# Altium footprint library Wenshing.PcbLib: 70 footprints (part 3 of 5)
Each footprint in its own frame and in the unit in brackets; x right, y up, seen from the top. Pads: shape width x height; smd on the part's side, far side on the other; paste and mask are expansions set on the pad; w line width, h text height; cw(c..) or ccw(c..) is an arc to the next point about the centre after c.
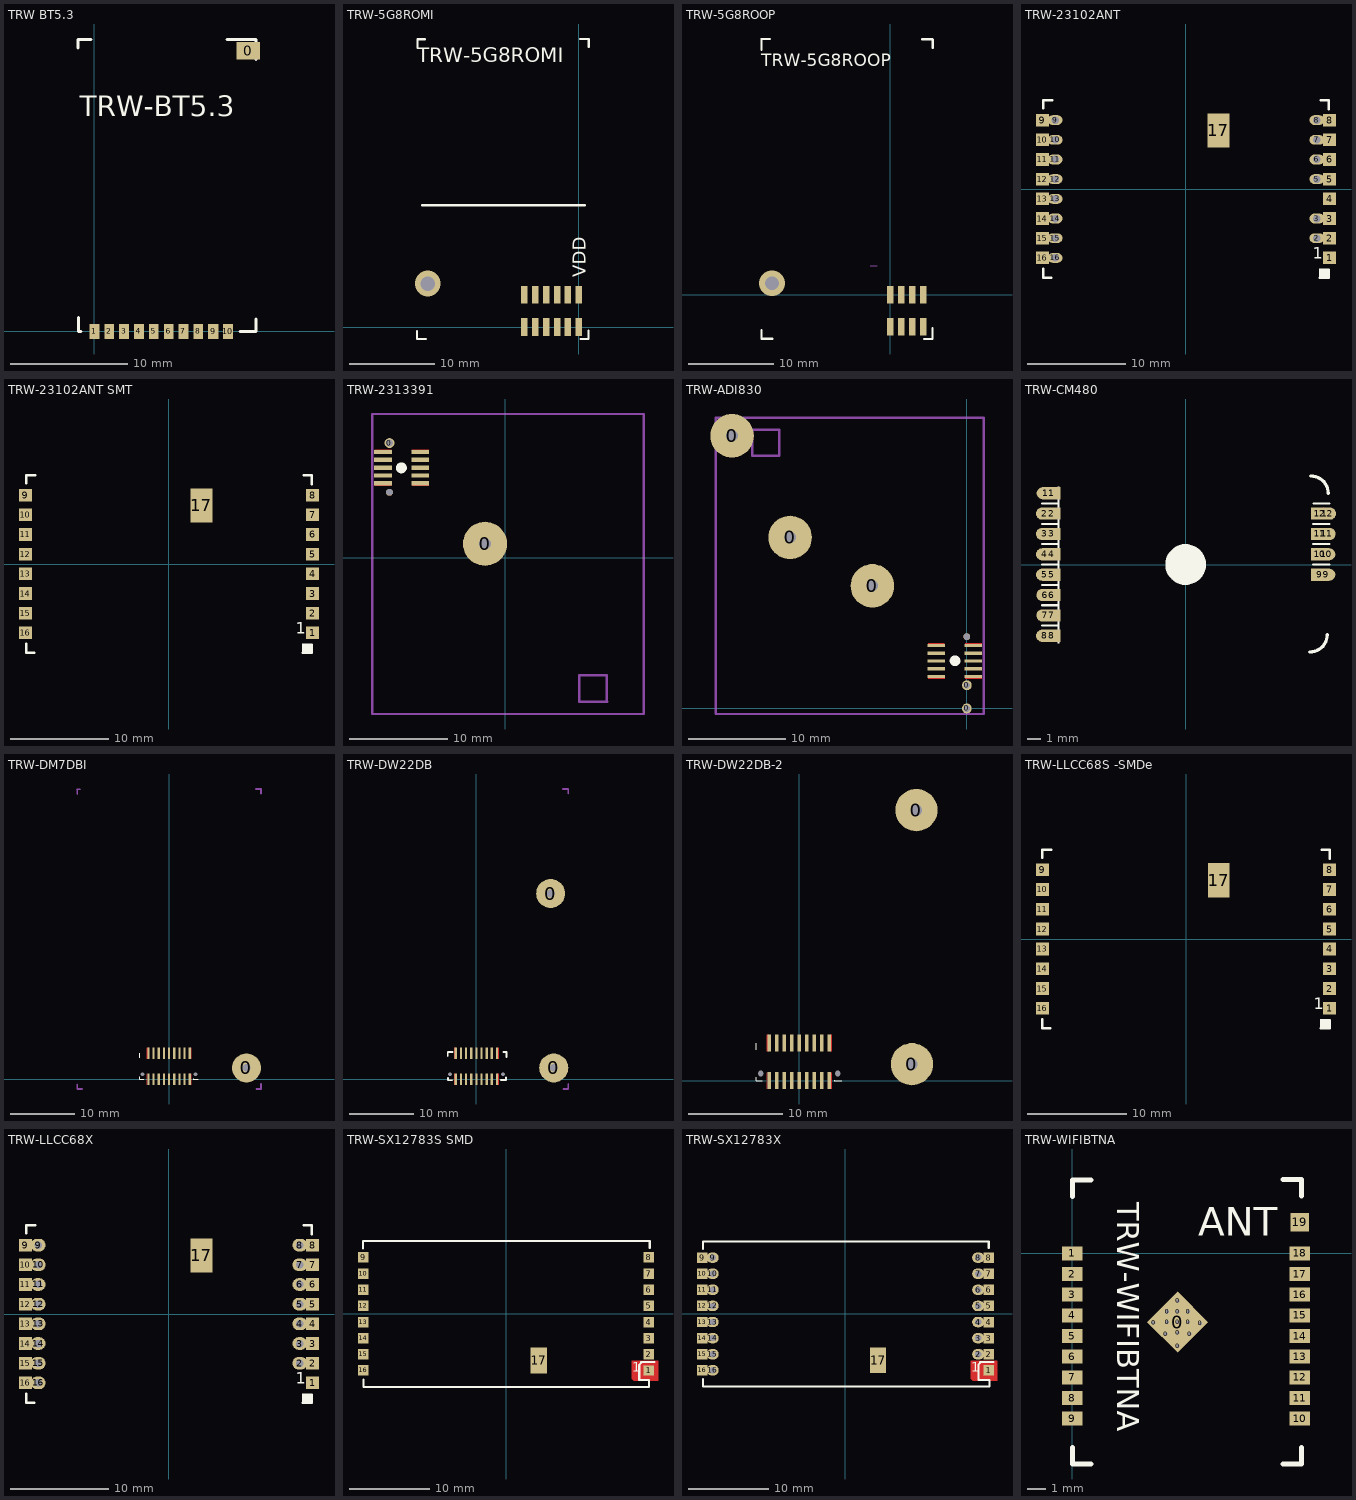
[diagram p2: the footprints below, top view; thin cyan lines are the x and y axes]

## TRW BT5.3 [mil]
pads (11):
  rect 78.74x60 smd: 0(518,946)
  rect 33x51.18 smd mask+3.94: 1(0,0) 2(50,0) 3(100,0) 4(150,0) 5(200,0) 6(250,0) 7(300,0) 8(350,0)
  rect 35x51 smd mask+3.94: 9(400,0) 10(450,0)
Top Overlay:
  lines w10: -55.01,955.01 -55.01,984.01 -11.01,984.01 ; -54.53,47.05 -54.53,-0.2 -44.69,-0.2 ; 445.99,984.01 544.99,984.01 544.99,916.01 ; 489.99,0.01 503.74,0.01 531.24,0.01 544.99,0.01 544.99,42.01
  text "TRW-BT5.3" at -50,701.39 h118.11
3D body "BT 5.3 MODULE v1.5.step": height 179.7, standoff -3.6, extent -50.98,-30 539.57,975

## TRW-5G8ROMI [mm] "5.8G RADAR RF MODULE WENSHING ELECTRO"
pads (12):
  rect 0.76x2.05 smd: 1(0,0) 2(0,3.75) 3(-1.27,0) 4(-1.27,3.75) 5(-2.54,0) 6(-2.54,3.75) 7(-3.81,0) 8(-3.81,3.75) 9(-5.08,0) 10(-5.08,3.75) 11(-6.35,0)
  rect 0.76x2.05 smd mask+0.051: 12(-6.35,3.75)
via -17.633,5.077 diameter 3 hole 1.7
Top Overlay:
  lines w0.254: -18.871,-0.497 -18.871,-1.397 -17.871,-1.397 ; -18.846,32.604 -18.846,33.604 -17.946,33.604 ; -18.321,14.228 0.704,14.228 ; 0.155,33.628 1.155,33.628 1.155,32.728 ; 0.229,-1.398 1.129,-1.398 1.129,-0.398
  text "VDD" at 0.821,5.804 h1.52
  text "TRW-5G8ROMI" at -18.835,30.359 h2.92

## TRW-5G8ROOP [mm]
pads (8):
  rect 0.76x2.05 smd: 1(0,0) 2(0,-3.75) 3(1.27,0) 4(1.27,-3.75) 5(2.54,0) 6(2.54,-3.75) 7(3.81,0) 8(3.81,-3.75)
via -13.843,1.33 diameter 3 hole 1.6
Top Overlay:
  lines w0.254: -15.082,28.599 -15.082,28.912 -15.082,29.538 -15.082,29.851 -15.059,29.874 ; -15.08,-5.101 -15.08,-4.149 ; -15.079,-5.126 -15.056,-5.149 -14.743,-5.149 -14.117,-5.149 -13.804,-5.149 ; -15.034,29.875 -14.082,29.875 ; 3.666,29.855 3.979,29.855 4.605,29.855 4.918,29.855 4.941,29.832 ; 3.922,-5.169 4.874,-5.169 ; 4.899,-5.168 4.922,-5.145 4.922,-4.832 4.922,-4.206 4.922,-3.893 ; 4.942,28.855 4.942,29.807
  text "TRW-5G8ROOP" at -15.094,26.182 h2.5
Mechanical 15:
  lines w0.025: -2.343,3.373 -1.543,3.373

## TRW-23102ANT [mm]
pads (32):
  rect 1.3x1.3 smd: 1(14.6,-7) 2(14.6,-5) 3(14.6,-3) 4(14.6,-1) 5(14.6,1) 6(14.6,3) 7(14.6,5) 8(14.6,7) 9(-14.6,7) 10(-14.6,5) 11(-14.6,3) 12(-14.6,1) 13(-14.6,-1) 14(-14.6,-3) 15(-14.6,-5) 16(-14.6,-7)
  oval 1.5x1 / inner round 1 / far side oval 1.5x1.2 hole 0.762 mask+0.102: 2(13.3,-5) 3(13.3,-3) 5(13.3,1) 6(13.3,3) 7(13.3,5) 8(13.3,7) 9(-13.3,7) 10(-13.3,5) 11(-13.3,3) 12(-13.3,1) 13(-13.3,-1) 14(-13.3,-3) 15(-13.3,-5) 16(-13.3,-7)
  rrect50% 0x0 all layers, no hole mask+0.102: 8(13.3,-7)
  rect 2.2x3.5 smd: 17(3.3,5.95)
Top Overlay:
  rectangle: 13.513,-9 14.5,-8.103
  lines w0.254: -14.5,-8.1 -14.5,-9 -13.7,-9 ; -14.5,8.2 -14.5,9 -13.6,9 ; 13.6,-9 14.5,-9 14.5,-8.2 ; 13.7,9 14.5,9 14.5,8.1
  text "1" at 12.907,-7.493 h2.03

## TRW-23102ANT SMT [mm]
pads (18):
  rect 1.3x1.3 smd: 1(14.6,-7) 2(14.6,-5) 3(14.6,-3) 4(14.6,-1) 5(14.6,1) 6(14.6,3) 7(14.6,5) 8(14.6,7) 9(-14.6,7) 10(-14.6,5) 11(-14.6,3) 12(-14.6,1) 13(-14.6,-1) 14(-14.6,-3) 15(-14.6,-5) 16(-14.6,-7)
  rrect50% 0x0 all layers, no hole mask+0.102: 8(13.3,-7)
  rect 2.2x3.5 smd: 17(3.3,5.95)
Top Overlay:
  rectangle: 13.513,-9 14.5,-8.103
  lines w0.254: -14.5,-8.1 -14.5,-9 -13.7,-9 ; -14.5,8.2 -14.5,9 -13.6,9 ; 13.6,-9 14.5,-9 14.5,-8.2 ; 13.7,9 14.5,9 14.5,8.1
  text "1" at 12.907,-7.493 h2.03

## TRW-2313391 [mm]
pads (15):
  round 1.016 hole 0.7: 0(-11.8,11.686)
  round 4.5 / inner round 2 / far side round 2 hole 1.2 mask+0.102: 0(-2.044,1.414)
  round 0 all layers, no hole mask+0.102: 0(6.456,-3.587) 0(12.456,-14.086)
  rect 1.8x0.45 smd: 1(-12.456,7.578) 2(-12.456,8.378) 3(-12.456,9.178) 4(-12.456,9.978) 5(-12.456,10.778) 12(-8.656,10.778) 13(-8.656,9.978) 14(-8.656,9.178) 15(-8.656,8.378) 16(-8.656,7.578)
  round 0.7 / inner round 0.7 / far side round 1.016 hole 0.7: 1(-11.8,6.669)
Top Layer:
  rectangle: -13.35,10.937 -11.597,11.038
  rectangle: -9.54,10.937 -7.787,11.038
  rectangle: -9.514,7.304 -7.787,7.406
  rectangle: -13.35,7.304 -11.597,7.406
Top Overlay:
  circle w0.6: c-10.581,9.159 r0.25
Bottom Overlay:
  lines w0.051: -12.534,11.846 -12.534,12.446 -12.184,12.446 ; -12.531,7.053 -12.556,7.028 -12.556,6.228 -12.181,6.228 ; -9.331,6.253 -8.556,6.253 -8.556,6.728 ; -9.259,12.446 -8.559,12.446 -8.534,12.421 -8.534,11.771
Mechanical 10:
  lines w0.254: -13.549,-15.951 -13.549,14.656 14.137,14.656 14.137,-15.951 -13.549,-15.951 ; 7.584,-14.706 7.584,-12.014 10.378,-12.014 10.378,-14.706 10.403,-14.706 7.584,-14.706
3D body "TRW-ADI835.step": height 0, standoff -3.8, extent -13.477,-16.038 14.209,14.569

## TRW-ADI830 [mm] "RF MODULE"
pads (16):
  round 4.5 / inner round 2 / far side round 2 hole 1.2 mask+0.102: 0(-24.256,28.172) 0(-18.256,17.673) 0(-9.756,12.672)
  round 1.016 hole 0.7: 0(0,0) 0(0,2.4)
  round 0.7 / inner round 0.7 / far side round 1.016 hole 0.7: 1(0,7.417)
  rect 1.8x0.35 smd: 1(0.655,6.508) 2(0.655,5.708) 3(0.655,4.908) 4(0.655,4.108) 5(0.655,3.308) 6(-3.145,3.308) 7(-3.145,4.108) 8(-3.145,4.908) 9(-3.145,5.708) 10(-3.145,6.508)
Top Layer:
  region: 1.549,3.15 -0.203,3.15 -0.203,3.048 1.549,3.048
  region: -2.261,3.15 -4.013,3.15 -4.013,3.048 -2.261,3.048
  region: -2.286,6.782 -4.013,6.782 -4.013,6.68 -2.286,6.68
  region: 1.549,6.782 -0.203,6.782 -0.203,6.68 1.549,6.68
Top Overlay:
  circle w0.6: c-1.219,4.928 r0.25
Bottom Overlay:
  lines w0.051: -3.245,0.233 -3.245,-0.417 -3.22,-0.442 -2.52,-0.442 ; -3.245,7.358 -3.245,7.833 -2.47,7.833 ; 0.38,7.858 0.755,7.858 0.755,7.058 0.73,7.033 ; 0.405,-0.442 0.755,-0.442 0.755,0.158
Mechanical 10:
  lines w0.254: -25.938,-0.57 -25.938,30.037 1.748,30.037 1.748,-0.57 -25.938,-0.57 ; -22.204,28.792 -22.178,28.792 -22.178,26.1 -19.384,26.1 -19.384,28.792 -22.204,28.792
3D body: height 0, standoff -3, extent -1.789,0.351 -0.69,6.949
3D body: height 0, standoff -3, extent -3.439,-0.649 0.005,7.949
3D body: height 0, standoff -3, extent 0.006,-0.649 0.96,7.949
3D body "TRW-ADI835.step": height 0, standoff -3.8, extent -26.01,-0.483 1.676,30.124
3D body: height 0.5, standoff 0, extent -3.57,6.358 -3.245,6.658
3D body: height 0.5, standoff 0, extent -3.57,5.558 -3.245,5.858
3D body: height 0.5, standoff 0, extent -3.57,4.758 -3.245,5.058
3D body: height 0.5, standoff 0, extent -3.57,3.958 -3.245,4.258
3D body: height 0.5, standoff 0, extent -3.57,3.158 -3.245,3.458
3D body: height 0.5, standoff 0, extent -3.57,2.358 -3.245,2.658
3D body: height 0.5, standoff 0, extent -3.57,1.558 -3.245,1.858
3D body: height 0.5, standoff 0, extent -3.582,0.758 -3.257,1.058
3D body: height 0.5, standoff 0, extent 0.755,0.758 1.08,1.058
3D body: height 0.5, standoff 0, extent 0.755,1.558 1.08,1.858
3D body: height 0.5, standoff 0, extent 0.755,2.358 1.08,2.658
3D body: height 0.5, standoff 0, extent 0.755,3.158 1.08,3.458
3D body: height 0.5, standoff 0, extent 0.755,3.958 1.08,4.258
3D body: height 0.5, standoff 0, extent 0.755,4.758 1.08,5.058
3D body: height 0.5, standoff 0, extent 0.755,5.558 1.08,5.858
3D body: height 0.5, standoff 0, extent 0.755,6.358 1.08,6.658

## TRW-CM480 [mm] "RF MODULE 480MHZ ASK/FSK"
pads (24):
  oval 1.3x0.9 smd: 1(-10.325,5.25) 2(-10.375,3.75) 3(-10.375,2.25) 4(-10.375,0.75) 5(-10.375,-0.75) 6(-10.35,-2.25) 7(-10.35,-3.75) 8(-10.375,-5.25) 9(10.375,-0.75) 10(10.375,0.75) 11(10.4,2.25) 12(10.425,3.75)
  rect 1.3x0.9 smd: 1(-9.877,5.25) 2(-9.877,3.75) 3(-9.877,2.25) 4(-9.877,0.75) 5(-9.877,-0.75) 6(-9.877,-2.25) 7(-9.877,-3.75) 8(-9.877,-5.25) 9(9.877,-0.75) 10(9.877,0.75) 11(9.877,2.25) 12(9.877,3.75)
Top Layer:
  region: 10.318,3.625 10.29,3.652 10.265,3.672 10.243,3.687 10.224,3.696 10.208,3.699 10.195,3.696 10.185,3.687 10.177,3.672 10.173,3.652 10.171,3.625 10.171,4.2 10.173,4.172 10.177,4.143 10.185,4.115 10.195,4.086 10.208,4.058 10.224,4.029 10.243,4 10.265,3.971 10.29,3.942 10.318,3.913
Top Overlay:
  circle w1.5: c0,0 r0.75
  rectangle: -9.429,-5.825 -9.302,5.75
  lines w0.152: -10.577,-4.5 -9.377,-4.5 ; -10.577,-3 -9.377,-3 ; -10.577,-1.5 -9.377,-1.5 ; -10.577,0 -9.402,0 ; -10.577,1.5 -9.377,1.5 ; -10.577,3 -9.377,3 ; -10.577,4.5 -9.377,4.5 ; 9.377,0 10.577,0 ; 9.377,1.5 10.577,1.5 ; 9.377,3 10.577,3 ; 9.403,4.5 10.577,4.5
  lines w0.254: 9.155,-6.445 ccw(c9.155,-5.175) 10.425,-5.175 ; 9.23,6.52 cw(c9.23,5.25) 10.5,5.25
3D body "TRWCM480.step": height 2.27, standoff 0.35, extent -10.156,-6.654 10.606,6.6

## TRW-DM7DBI [mm] "3.89G-7GHZ RF MODULE"
pads (21):
  round 0 hole 0.6: 0(-4.1,0.751) 0(4.1,0.751)
  round 4.5 hole 1.2: 0(11.995,1.741)
  rect 0.35x1.8 smd: 1(3.2,0) 2(2.4,0) 3(1.6,0) 4(0.8,0) 5(0,0) 6(-0.8,0) 7(-1.6,0) 8(-2.4,0) 9(-3.2,0) 10(-3.2,4) 11(-2.4,4) 12(-1.6,4) 13(-0.8,4) 14(0,4) 15(0.8,4) 16(1.6,4) 17(2.4,4) 18(3.2,4)
Top Layer:
  region: 3.473,-0.889 3.473,0.882 3.2,0.882 3.2,-0.889
  region: 3.505,3.099 3.505,4.902 3.353,4.902 3.353,3.099
  region: -3.36,-0.889 -3.36,0.882 -3.461,0.882 -3.461,-0.889
  region: -3.2,3.099 -3.2,4.902 -3.48,4.902 -3.48,3.099
Top Overlay:
  lines w0.051: -4.55,0.35 -4.55,0 -3.95,0 ; -4.55,3.275 -4.55,3.975 ; 3.725,0.025 3.75,0 4.55,0
Bottom Overlay:
  lines w0.051: -4.546,0.351 -4.546,0.001 -3.946,0.001 ; -4.546,3.276 -4.546,3.976 -4.521,4.001 -3.871,4.001 ; 3.729,0.026 3.754,0.001 4.554,0.001 4.554,0.376 ; 4.054,4.001 4.529,4.001 4.529,3.226
Mechanical 1:
  lines w0.254: -14.264,-0.793 -14.257,-0.793 ; -14.249,44.196 -14.249,44.971 -14.257,44.971 -14.275,44.971 -13.792,44.971 ; -13.451,-1.529 -14.257,-1.529 -14.257,-0.793 ; 13.437,44.983 14.243,44.983 14.243,44.247 ; 13.506,-1.536 13.506,-1.529 ; 14.243,-0.723 14.243,-1.529 13.506,-1.529 ; 14.249,44.247 14.243,44.247 ; -14.257,-0.793 -14.257,-0.793 ; 13.506,-1.529 13.506,-1.529 ; 14.243,44.247 14.243,44.247
3D body "TRW-DW1000.step": height -3, standoff -6.71, extent -10.933,-1.411 14.45,43.028
3D body: height 3, standoff 0, extent -4.4,-0.205 4.641,0.749
3D body: height 3, standoff 0, extent -2.958,1.445 3.641,2.544
3D body: height 3, standoff 0, extent -4.4,0.751 4.641,4.194

## TRW-DW22DB [mm] "3.89G-7GHZ RF MODULE"
pads (22):
  round 0 hole 0.6: 0(-4.1,0.751) 0(4.1,0.751)
  round 4.5 hole 1.2: 0(11.519,28.778) 0(11.995,1.741)
  rect 0.35x1.8 smd: 1(3.2,0) 2(2.4,0) 3(1.6,0) 4(0.8,0) 5(0,0) 6(-0.8,0) 7(-1.6,0) 8(-2.4,0) 9(-3.2,0) 10(-3.2,4) 11(-2.4,4) 12(-1.6,4) 13(-0.8,4) 14(0,4) 15(0.8,4) 16(1.6,4) 17(2.4,4) 18(3.2,4)
Top Layer:
  region: -3.2,3.099 -3.2,4.902 -3.48,4.902 -3.48,3.099
  region: -3.36,-0.889 -3.36,0.882 -3.461,0.882 -3.461,-0.889
  region: 3.505,3.099 3.505,4.902 3.353,4.902 3.353,3.099
  region: 3.473,-0.889 3.473,0.882 3.2,0.882 3.2,-0.889
Top Overlay:
  lines w0.051: -4.445,4.191 -4.42,4.216
  lines w0.3: -4.445,3.541 -4.445,4.191 ; -4.42,4.216 -3.72,4.216 ; -4.389,0.172 -4.389,-0.178 -3.789,-0.178 ; 3.797,-0.137 4.597,-0.137 4.597,0.238 ; 4.173,4.197 4.648,4.198 4.648,3.422
Mechanical 1:
  lines w0.254: 13.437,44.983 14.243,44.983 14.243,44.247 ; 13.506,-1.536 13.506,-1.529 ; 14.243,-0.723 14.243,-1.529 13.506,-1.529 ; 14.249,44.247 14.243,44.247 ; 13.506,-1.529 13.506,-1.529 ; 14.243,44.247 14.243,44.247
3D body: height 3, standoff 0, extent -4.4,0.751 4.641,4.194
3D body: height 3, standoff 0, extent -2.958,1.445 3.641,2.544
3D body: height 3, standoff 0, extent -4.4,-0.205 4.641,0.749
3D body "TRW-DW22DBm全向b.step": height 0, standoff -4.96, extent -9.825,-1.9 13.938,48.65

## TRW-DW22DB-2 [mm] "3.89G-7GHZ RF MODULE"
pads (22):
  round 0 hole 0.6: 0(-4.1,0.751) 0(4.1,0.751)
  round 4.5 hole 1.2: 0(11.995,1.741) 0(12.471,28.778)
  rect 0.35x1.8 smd: 1(3.2,0) 2(2.4,0) 3(1.6,0) 4(0.8,0) 5(0,0) 6(-0.8,0) 7(-1.6,0) 8(-2.4,0) 9(-3.2,0) 10(-3.2,4) 11(-2.4,4) 12(-1.6,4) 13(-0.8,4) 14(0,4) 15(0.8,4) 16(1.6,4) 17(2.4,4) 18(3.2,4)
Top Layer:
  region: -3.2,3.099 -3.2,4.902 -3.48,4.902 -3.48,3.099
  region: -3.36,-0.889 -3.36,0.882 -3.461,0.882 -3.461,-0.889
  region: 3.505,3.099 3.505,4.902 3.353,4.902 3.353,3.099
  region: 3.473,-0.889 3.473,0.882 3.2,0.882 3.2,-0.889
Top Overlay:
  lines w0.051: -4.55,0.35 -4.55,0 -3.95,0 ; -4.55,3.275 -4.55,3.975 ; 3.725,0.025 3.75,0 4.55,0
Bottom Overlay:
  lines w0.051: -4.546,0.351 -4.546,0.001 -3.946,0.001 ; -4.546,3.276 -4.546,3.976 -4.521,4.001 -3.871,4.001 ; 3.729,0.026 3.754,0.001 4.554,0.001 4.554,0.376 ; 4.054,4.001 4.529,4.001 4.529,3.226
3D body: height 3, standoff 0, extent -4.4,0.751 4.641,4.194
3D body: height 3, standoff 0, extent -2.958,1.445 3.641,2.544
3D body: height 3, standoff 0, extent -4.4,-0.205 4.641,0.749
3D body "TRW-DW22.step": height 4.96, standoff 0, extent -10.139,-1.449 15.222,57.506

## TRW-LLCC68S -SMDe [mm]
pads (18):
  rect 1.3x1.3 smd: 1(14.5,-7) 2(14.5,-5) 3(14.5,-3) 4(14.5,-1) 5(14.5,1) 6(14.5,3) 7(14.5,5) 8(14.5,7) 9(-14.5,7) 10(-14.5,5) 11(-14.5,3) 12(-14.5,1) 13(-14.5,-1) 14(-14.5,-3) 15(-14.5,-5) 16(-14.5,-7)
  rrect50% 0x0 all layers, no hole mask+0.102: 8(13.3,-7)
  rect 2.2x3.5 smd: 17(3.3,5.95)
Top Overlay:
  rectangle: 13.513,-9 14.5,-8.103
  lines w0.254: -14.5,-8.1 -14.5,-9 -13.7,-9 ; -14.5,8.2 -14.5,9 -13.6,9 ; 13.6,-9 14.5,-9 14.5,-8.2 ; 13.7,9 14.5,9 14.5,8.1
  text "1" at 12.907,-7.493 h2.03

## TRW-LLCC68X [mm]
pads (33):
  rect 1.3x1.3 smd: 1(14.6,-7) 2(14.6,-5) 3(14.6,-3) 4(14.6,-1) 5(14.6,1) 6(14.6,3) 7(14.6,5) 8(14.6,7) 9(-14.6,7) 10(-14.6,5) 11(-14.6,3) 12(-14.6,1) 13(-14.6,-1) 14(-14.6,-3) 15(-14.6,-5) 16(-14.6,-7)
  oval 1.5x1.3 / inner round 1 / far side oval 1.6x1.3 hole 0.762 mask+0.102: 2(13.3,-5) 3(13.3,-3) 4(13.3,-1) 5(13.3,1) 6(13.3,3) 7(13.3,5) 8(13.3,7) 9(-13.3,7) 10(-13.3,5) 11(-13.3,3) 12(-13.3,1) 13(-13.3,-1) 14(-13.3,-3) 15(-13.3,-5) 16(-13.3,-7)
  rrect50% 0x0 all layers, no hole mask+0.102: 8(13.3,-7)
  rect 2.2x3.5 smd: 17(3.3,5.95)
Top Overlay:
  rectangle: 13.513,-9 14.5,-8.103
  lines w0.254: -14.5,-8.1 -14.5,-9 -13.7,-9 ; -14.5,8.2 -14.5,9 -13.6,9 ; 13.6,-9 14.5,-9 14.5,-8.2 ; 13.7,9 14.5,9 14.5,8.1
  text "1" at 12.907,-7.493 h2.03

## TRW-SX12783S SMD [mm]
pads (17):
  rect 1.3x1.3 smd mask+0.102: 1(17.691,-7.002) 2(17.691,-5.002) 3(17.691,-3.002) 4(17.691,-1.002) 5(17.691,0.998) 6(17.691,2.998) 7(17.691,4.998) 8(17.691,6.998) 9(-17.691,7.002) 10(-17.691,5.002) 11(-17.691,3.002) 12(-17.691,1.002) 13(-17.691,-0.998) 14(-17.691,-2.998) 15(-17.691,-4.998) 16(-17.691,-6.998)
  rect 2x3.2 smd: 17(4.059,-5.748)
Top Layer:
  pour cut-out: 18.825,-5.8 15.575,-5.8 15.575,-8.05 15.825,-8.3 18.825,-8.3
  lines w0.305: -17.741,5.002 -17.741,5.002
Top Overlay:
  lines w0.254: -17.704,8.1 -17.704,9.014 17.8,9.014 17.8,8.176 ; -17.678,-8.105 -17.678,-9.02 17.704,-9.02 17.704,-8.182 16.5,-8.182 16.5,-7.379 16.5,-6.3 16.828,-5.972 ; 16.728,-5.972 18.4,-5.972
  text "1" at 15.621,-7.6 h2.03

## TRW-SX12783X [mm]
pads (32):
  rect 1.3x1.3 smd mask+0.102: 1(17.791,-7.002) 2(17.791,-5.002) 3(17.791,-3.002) 4(17.791,-1.002) 5(17.791,0.998) 6(17.791,2.998) 7(17.791,4.998) 8(17.791,6.998) 9(-17.791,7.002) 10(-17.791,5.002) 11(-17.791,3.002) 12(-17.791,1.002) 13(-17.791,-0.998) 14(-17.791,-2.998) 15(-17.791,-4.998) 16(-17.791,-6.998)
  oval 1.5x1.3 / inner round 1 / far side oval 1.5x1.3 hole 0.762 mask+0.102: 2(16.491,-5.002) 3(16.491,-3.002) 4(16.491,-1.002) 5(16.491,0.998) 6(16.491,2.998) 7(16.491,4.998) 8(16.491,6.998) 9(-16.491,7.002) 10(-16.491,5.002) 11(-16.491,3.002) 12(-16.491,1.002) 13(-16.491,-0.998) 14(-16.491,-2.998) 15(-16.491,-4.998) 16(-16.491,-6.998)
  rect 2x3.2 smd: 17(4.059,-5.748)
Top Layer:
  pour cut-out: 18.825,-5.8 15.575,-5.8 15.575,-8.05 15.825,-8.3 18.825,-8.3
  lines w0.305: -16.851,-7.002 -16.849,-7.004
Top Overlay:
  lines w0.254: -17.704,8.1 -17.704,9.014 17.8,9.014 17.8,8.176 ; -17.678,-8.105 -17.678,-9.02 17.9,-9.02 17.9,-8.181 16.5,-8.181 16.5,-7.379 16.5,-6.3 16.828,-5.972 ; 16.728,-5.972 18.4,-5.972
  text "1" at 15.621,-7.6 h2.03

## TRW-WIFIBTNA [mm] "WIFI +BT MODULE"
pads (33):
  round 0.45 hole 0.2 mask+0.102: 0(4.323,-3.693) 0(4.971,-4.298) 0(5.042,-3.096) 0(5.042,-3.662) 0(5.608,-4.935) 0(5.608,-4.228) 0(5.608,-3.662) 0(5.608,-3.096) 0(5.608,-2.531) 0(6.173,-3.662) 0(6.173,-3.096) 0(6.244,-4.298) 0(6.81,-3.733)
  rect 2.3x2.3 all layers, no hole rot 135 mask+0.08: 0(5.608,-3.662)
  rect 1.1x0.75 smd mask+0.102: 1(0,0) 2(0,-1.1) 3(0,-2.2) 4(0,-3.3) 5(0,-4.4) 6(0,-5.5) 7(0,-6.6) 8(0,-7.7) 9(0,-8.8) 10(12.1,-8.8) 11(12.1,-7.7) 12(12.1,-6.6) 13(12.1,-5.5) 14(12.1,-4.4) 15(12.1,-3.3) 16(12.1,-2.2) 17(12.1,-1.1) 18(12.1,0)
  rect 1x1 smd mask+0.102: 19(12.1,1.65)
Top Layer:
  region: 5.333,-4.46 5.348,-4.444 5.361,-4.427 5.371,-4.411 5.38,-4.393 5.386,-4.375 5.391,-4.356 5.393,-4.337 5.393,-4.317 5.392,-4.297 5.388,-4.276 5.652,-4.448 5.629,-4.453 5.587,-4.466 5.567,-4.474 5.548,-4.483 5.53,-4.493 5.513,-4.504 5.496,-4.516 5.48,-4.529 5.466,-4.543
  region: 5.536,-3.873 5.521,-3.89 5.512,-3.907 5.509,-3.922 5.512,-3.937 5.522,-3.951 5.537,-3.964 5.558,-3.976 5.584,-3.988 5.617,-3.998 5.656,-4.008 5.441,-4.077 5.3,-4.397
  region: 5.455,-4.062 5.226,-4.183 5.3,-4.397 5.407,-4.329
  region: 5.353,-4.343 5.124,-4.464 5.172,-4.197 5.279,-4.129
  lines w0.152: 5.334,-2.54 5.359,-2.54 ; 5.608,-4.293 5.608,-4.228 5.608,-3.945 5.608,-3.662 ; 12.012,-5.412 12.1,-5.5
Top Overlay:
  lines w0.254: 0.005,-10.323 0.005,-11.212 0.995,-11.212 ; 0.005,3.012 0.005,3.901 0.995,3.901 ; 11.206,-11.212 12.197,-11.212 12.197,-10.323 ; 11.206,3.927 12.197,3.927 12.197,3.038
  text "TRW-WIFIBTNA" at 1.995,2.723 h2.03
  text "ANT" at 6.706,0.94 h1.52
3D body "TRW-WIFIBTNA.step": height 2.6, standoff -0.02, extent 0.005,-11.136 12.197,3.941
